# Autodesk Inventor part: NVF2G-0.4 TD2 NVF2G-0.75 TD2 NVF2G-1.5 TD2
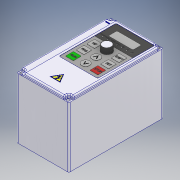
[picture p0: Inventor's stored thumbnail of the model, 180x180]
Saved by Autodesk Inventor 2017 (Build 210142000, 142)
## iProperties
Part Number: NVF2G-0.4 TD2 NVF2G-0.75 TD2 NVF2G-1.5 TD2
Material: Типовые
Document SubType Name: Modeling
Designer: RSagdiev
Density: 1 g/cm^3
Appearance: По умолчанию
Author: RSagdiev
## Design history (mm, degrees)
sketch "Эскиз1"
  geometry: L1 (0, 0)-(44.679, 0) reference; L2 (0, 0)-(0, 56.035) reference; L3 (0, 0)-(154, 0); L4 (154, 0)-(154, 98.6); L5 (154, 98.6)-(0, 98.6); L6 (0, 98.6)-(0, 0)
  constraints: 12 end point, 3 horizontal, 2 parallel, 2 vertical, 1 perpendicular
  dimensions: "d0" = 154 distance of L5.end L4.end; "d1" = 98.6 distance of L4.end L3.end
extrude "Выдавливание1" new body sketch "Эскиз1" stored distance "d2" = 85; taper "d3" = 0 deg
sketch "Эскиз2"
  geometry: L1 (0, 0)-(0, 154) reference; L2 (85, 0)-(85, 154) reference; L3 (0, 154)-(7, 154); L4 (85, 154)-(85, 147); L5 (85, 0)-(78, 0); L6 (0, 0)-(0, 7); L7 (0, 154)-(85, 154) reference; L8 (0, 154)-(7, 154); L9 (7, 154)-(7, 147); L10 (7, 147)-(0, 147); L11 (0, 147)-(0, 154); L12 (85, 154)-(78, 154); L13 (78, 154)-(78, 147); L14 (78, 147)-(85, 147); L15 (85, 147)-(85, 154); L16 (0, 0)-(85, 0) reference; L17 (0, 0)-(7, 0); L18 (7, 0)-(7, 7); L19 (7, 7)-(0, 7); L20 (0, 7)-(0, 0); L21 (85, 0)-(78, 0); L22 (78, 0)-(78, 7); L23 (78, 7)-(85, 7); L24 (85, 7)-(85, 0); L25 (7, 154)-(78, 154); L26 (0, 147)-(0, 154); L27 (78, 154)-(85, 154); L28 (85, 147)-(85, 7); L29 (78, 0)-(7, 0); L30 (85, 7)-(85, 0); L31 (7, 0)-(0, 0); L32 (0, 7)-(0, 147); 1 further point
  constraints: 56 end point, 26 parallel, 13 perpendicular, 7 horizontal
  dimensions: "d4" = 7 distance of L9.end L10.end; "d5" = 7 distance of L3.end L9.end (= d4); "d6" = 7 distance of L4.end L13.end (= d4); "d7" = 7 distance of L13.end L12.end (= d4); "d8" = 7 distance of L6.end L18.end (= d4); "d9" = 7 distance of L18.end L17.end (= d4); "d10" = 7 distance of L22.end L23.end (= d4); "d11" = 7 distance of L5.end L22.end (= d4)
extrude "Выдавливание2" new body sketch "Эскиз2" distance "d12" = 4; taper "d13" = 0 deg
chamfer "Фаска1" distance "d14" = 4; stored, may be unused: second distance "d15" = 2, angle "d16" = 45 deg
sketch "Эскиз3"
  geometry: L1 (7, 150)-(11.5, 150); L2 (7, 150)-(7, 147); L3 (7, 147)-(0, 147); L4 (0, 147)-(0, 7); L5 (0, 7)-(7, 7); L6 (7, 7)-(7, 0); L7 (7, 0)-(11.5, 0); L8 (78, 0)-(78, 7); L9 (78, 7)-(85, 7); L10 (85, 7)-(85, 147); L11 (85, 147)-(78, 147); L12 (78, 147)-(78, 150); L13 (7, 150)-(78, 150) reference; L14 (11.5, 150)-(11.5, 0); L15 (0, 0)-(85, 0) reference; L16 (11.5, 150)-(78, 150); L17 (11.5, 0)-(78, 0); 1 further point
  constraints: 10 end point, 2 perpendicular, 2 point on line
  dimensions: "d19" = 73.5 distance between parallel lines of L14 L10
extrude "Выдавливание3" new body sketch "Эскиз3" distance "d17" = 2; taper "d18" = 0 deg
sketch "Эскиз4"
  geometry: L1 (78, 145)-(19, 145); L2 (17, 143)-(17, 54); L3 (19, 52)-(78, 52); L4 (80, 54)-(80, 143); L5 (85, 7)-(85, 147) reference; L6 (7, 150)-(78, 150) reference; A1 r 2 centre (19, 143) between (19, 145) and (17, 143); A2 r 2 centre (78, 143) between (80, 143) and (78, 145); A3 r 2 centre (78, 54) between (78, 52) and (80, 54); A4 r 2 centre (19, 54) between (17, 54) and (19, 52); 4 further points
  constraints: 8 end point, 8 point on circle, 8 tangent, 6 point on line, 4 centre point, 3 equal radius, 2 parallel, 1 horizontal, 1 perpendicular
  dimensions: "d20" = 63 distance of point (80, 52) point (17, 52); "d21" = 93 distance of point (17, 52) point (17, 145); "d22" = 5 distance between parallel lines of L4 L5; "d23" = 5 distance between parallel lines of L6 L1; "d24" = 2 radius of A1
extrude "Выдавливание4" cut sketch "Эскиз4" distance "d25" = 0.6; taper "d26" = 0 deg
sketch "Эскиз5"
  geometry: L1 (0, 154)-(85, 154) reference; L2 (0, 0)-(0, 154) reference; L3 (85, 154)-(85, 0) reference; L4 (0, 0)-(85, 0) reference; C1 r 2.5 at (4.5, 150.5); C2 r 2.5 at (80.5, 150.5); C3 r 2.5 at (4.5, 3.5); C4 r 2.5 at (80.5, 3.5); 1 further point
  constraints: 4 centre point
  dimensions: "d27" = 5 diameter of C1; "d28" = 3.5 distance from line of C1.centre L1; "d29" = 4.5 distance from line of C1.centre L2; "d30" = 5 diameter of C2; "d31" = 3.5 distance from line of C2.centre L1; "d32" = 4.5 distance from line of C2.centre L3; "d33" = 5 diameter of C3; "d34" = 3.5 distance from line of L4 C3.centre; "d35" = 4.5 distance from line of C3.centre L2; "d36" = 5 diameter of C4; "d37" = 4.5 distance from line of C4.centre L3; "d38" = 3.5 distance from line of C4.centre L4
extrude "Выдавливание5" cut sketch "Эскиз5" stored distance "d39" = 0.6; taper "d40" = 0 deg
fillet "Сопряжение1" dims "d41" = 2
fillet "Сопряжение2" dims "d42" = 2
sketch "Эскиз6"
  geometry: L1 (17, 54)-(17, 110); L2 (78, 52)-(19, 52); L3 (80, 143)-(80, 110); L4 (19, 145)-(78, 145); L5 (17, 54)-(17, 143) reference; L6 (17, 110)-(80, 110); L7 (80, 143)-(80, 54) reference; L8 (17, 110)-(17, 143); L9 (80, 110)-(80, 54); L10 (30.5, 121)-(66.5, 121); L11 (68.5, 123)-(68.5, 133); L12 (66.5, 135)-(30.5, 135); L13 (28.5, 133)-(28.5, 123); L14 (28.5, 121)-(68.5, 135); L15 (68.5, 121)-(28.5, 135); L16 (48.5, 98.5)-(48.5, 63.857); L17 (40.25, 98.5)-(40.25, 63.857); L18 (56.75, 63.857)-(56.75, 98.5); L19 (34, 105)-(23, 105); L20 (22, 104)-(22, 93); L21 (23, 92)-(34, 92); L22 (35, 93)-(35, 104); L23 (35, 105)-(22, 92); L24 (22, 105)-(35, 92); L25 (68.5, 123)-(68.5, 58.5); L26 (28.5, 98.5)-(75.409, 98.5); L27 (26.654, 81.179)-(72.729, 81.179); L28 (26.654, 63.857)-(71.963, 63.857); L29 (75, 93)-(75, 104); L30 (63, 92)-(74, 92); L31 (75, 105)-(62, 92); L32 (62, 105)-(75, 92); L33 (62, 104)-(62, 93); L34 (74, 105)-(63, 105); L35 (75, 75.679)-(75, 86.679); L36 (63, 74.679)-(74, 74.679); L37 (75, 87.679)-(62, 74.679); L38 (62, 87.679)-(75, 74.679); L39 (62, 86.679)-(62, 75.679); L40 (74, 87.679)-(63, 87.679); L41 (75, 58.357)-(75, 69.357); L42 (63, 57.357)-(74, 57.357); L43 (75, 70.357)-(62, 57.357); L44 (62, 70.357)-(75, 57.357); L45 (62, 69.357)-(62, 58.357); L46 (74, 70.357)-(63, 70.357); L47 (35, 58.357)-(35, 69.357); L48 (23, 57.357)-(34, 57.357); L49 (35, 70.357)-(22, 57.357); L50 (22, 70.357)-(35, 57.357); L51 (22, 69.357)-(22, 58.357); L52 (34, 70.357)-(23, 70.357); L53 (35, 75.679)-(35, 86.679); L54 (23, 74.679)-(34, 74.679); L55 (35, 87.679)-(22, 74.679); L56 (22, 87.679)-(35, 74.679); L57 (22, 86.679)-(22, 75.679); L58 (34, 87.679)-(23, 87.679); L59 (78, 52)-(19, 52) reference; L60 (80, 143)-(80, 54) reference; C1 r 6.5 at (48.5, 98.5); C2 r 6.5 at (48.5, 63.857); C3 r 6.5 at (48.5, 81.179); A1 r 2 centre (30.5, 133) between (30.5, 135) and (28.5, 133); A2 r 2 centre (66.5, 133) between (68.5, 133) and (66.5, 135); A3 r 2 centre (66.5, 123) between (66.5, 121) and (68.5, 123); A4 r 2 centre (30.5, 123) between (28.5, 123) and (30.5, 121); A5 r 8.25 centre (48.5, 98.5) between (56.75, 98.5) and (40.25, 98.5); A6 r 8.25 centre (48.5, 63.857) between (40.25, 63.857) and (56.75, 63.857); A7 r 1 centre (34, 104) between (35, 104) and (34, 105); A8 r 1 centre (34, 93) between (34, 92) and (35, 93); A9 r 1 centre (23, 93) between (22, 93) and (23, 92); A10 r 1 centre (23, 104) between (23, 105) and (22, 104); A11 r 1 centre (74, 93) between (74, 92) and (75, 93); A12 r 1 centre (74, 104) between (75, 104) and (74, 105); A13 r 1 centre (63, 104) between (63, 105) and (62, 104); A14 r 1 centre (63, 93) between (62, 93) and (63, 92); A15 r 1 centre (74, 75.679) between (74, 74.679) and (75, 75.679); A16 r 1 centre (74, 86.679) between (75, 86.679) and (74, 87.679); A17 r 1 centre (63, 86.679) between (63, 87.679) and (62, 86.679); A18 r 1 centre (63, 75.679) between (62, 75.679) and (63, 74.679); A19 r 1 centre (74, 58.357) between (74, 57.357) and (75, 58.357); A20 r 1 centre (74, 69.357) between (75, 69.357) and (74, 70.357); A21 r 1 centre (63, 69.357) between (63, 70.357) and (62, 69.357); A22 r 1 centre (63, 58.357) between (62, 58.357) and (63, 57.357); A23 r 1 centre (34, 58.357) between (34, 57.357) and (35, 58.357); A24 r 1 centre (34, 69.357) between (35, 69.357) and (34, 70.357); A25 r 1 centre (23, 69.357) between (23, 70.357) and (22, 69.357); A26 r 1 centre (23, 58.357) between (22, 58.357) and (23, 57.357); A27 r 1 centre (34, 75.679) between (34, 74.679) and (35, 75.679); A28 r 1 centre (34, 86.679) between (35, 86.679) and (34, 87.679); A29 r 1 centre (23, 86.679) between (23, 87.679) and (22, 86.679); A30 r 1 centre (23, 75.679) between (22, 75.679) and (23, 74.679); A31 r 2 centre (19, 143) between (19, 145) and (17, 143) reference; A32 r 2 centre (78, 143) between (80, 143) and (78, 145) reference; A33 r 2 centre (78, 54) between (78, 52) and (80, 54) reference; A34 r 2 centre (19, 54) between (17, 54) and (19, 52) reference; 13 further points
  constraints: 110 end point, 68 point on line, 60 point on circle, 60 tangent, 33 centre point, 21 equal radius, 15 midpoint, 15 parallel, 11 horizontal, 7 perpendicular, 3 coincident, 2 vertical
  dimensions: "d43" = 35 distance between parallel lines of L4 L6; "d44" = 40 distance of L15.end L14.end; "d45" = 14 distance of L14.end L15.start; "d46" = 10 distance between parallel lines of L4 L12; "d47" = 2 radius of A1; "d48" = 11.5 distance between parallel lines of L8 L13; "d49" = 16.5 diameter of A6; "d50" = 31.5 distance between parallel lines of L1 L16; "d51" = 11.5 distance from line of L6 L16.start; "d52" = 11.85714 distance from line of L2 L16.end; "d53" = 13 diameter of C1; "d54" = 13 diameter of C2; "d55" = 13 diameter of C3; "d56" = 13 distance of L24.end L23.end; "d57" = 13 distance of L23.end L24.start; "d58" = 1 radius of A7 (derived); "d59" = 11.5 distance from line of L6 L26.start; "d60" = 11.5 distance from line of L5 L26.start; "d61" = 13 distance of L32.end L31.end; "d62" = 13 distance of L31.end L32.start; "d63" = 1 radius of A12 (derived); "d64" = 13 distance of L38.end L37.end; "d65" = 13 distance of L37.end L38.start; "d66" = 1 radius of A16 (derived); "d67" = 13 distance of L44.end L43.end; "d68" = 13 distance of L43.end L44.start; "d69" = 1 radius of A20 (derived); "d70" = 13 distance of L50.end L49.end; "d71" = 13 distance of L49.end L50.start; "d72" = 1 radius of A24 (derived); "d73" = 13 distance of L56.end L55.end; "d74" = 13 distance of L55.end L56.start; "d75" = 1 radius of A28 (derived)
extrude "Выдавливание6" new body sketch "Эскиз6" distance "d76" = 0.3; taper "d77" = 0 deg
extrude "Выдавливание7" new body sketch "Эскиз6" distance "d78" = 0.6; taper "d79" = 0 deg
sketch "Эскиз7"
  geometry: L1 (17, 110)-(80, 110) reference; L2 (80, 143)-(80, 54) reference; L3 (17, 110)-(80, 110); L4 (80, 110)-(80, 110.1); L5 (80, 110.1)-(17, 110.1); L6 (17, 110.1)-(17, 110); 1 further point
  constraints: 8 end point, 2 parallel, 1 horizontal, 1 perpendicular, 1 point on line
  dimensions: "d80" = 0.1 distance of L4.end L3.end
extrude "Выдавливание8" cut sketch "Эскиз7" distance "d81" = 0.3; taper "d82" = 0 deg
sketch "Эскиз8" dims "d91" = 10
  geometry: L1 (17, 110.1)-(80, 110.1) reference; L2 (17, 54)-(17, 143) reference; C1 r 1 at (25, 115.1); C2 r 1 at (32.75, 115.1); C3 r 1 at (40.5, 115.1); C4 r 1 at (48.25, 115.1); C5 r 1 at (56, 115.1); C6 r 1 at (63.75, 115.1); C7 r 1 at (71.5, 115.1); 1 further point
  constraints: 7 centre point, 1 horizontal, 12 other
  dimensions: "d83" = 2 diameter of C1; "d84" = 5 distance from line of C1.centre L1; "d85" = 8 distance from line of C1.centre L2; "d88" = 7.75 distance of C1.centre C2.centre
extrude "Выдавливание9" join sketch "Эскиз8" distance "d93" = 0.3; taper "d94" = 0 deg
sketch "Эскиз9"
  geometry: C1 r 6.5 at (0, 0) reference; C2 r 7.5 at (0, 0); 1 further point
  constraints: 1 centre point, 1 coincident
  dimensions: "d95" = 15 diameter of C2
extrude "Выдавливание10" join sketch "Эскиз9" distance "d96" = 9.4; taper "d97" = -3 deg
sketch "Эскиз10"
  geometry: L1 (0, 7.331)-(0.619, 6.259); L2 (0.619, 6.259)-(-0.619, 6.259); L3 (-0.619, 6.259)-(0, 7.331); 2 further points
  constraints: 6 end point, 7 other
sketch "Эскиз11"
  geometry: L1 (0, 7.917)-(0.884, 6.386); L2 (0.884, 6.386)-(-0.884, 6.386); L3 (-0.884, 6.386)-(0, 7.917); 2 further points
  constraints: 6 end point, 7 other
feature "Лофт1" sketch "Эскиз10", "Эскиз11" dims "d98" = 0, "d99" = 90 deg, "d100" = 0, "d101" = 90 deg
sketch "Эскиз12"
  geometry: L1 (25.404, 100.254)-(31.624, 100.254); L2 (31.624, 100.254)-(31.624, 96.754); L3 (31.624, 96.754)-(25.404, 96.754); L4 (25.404, 96.754)-(25.404, 100.254); L5 (24.455, 83.155)-(33.309, 83.155); L6 (33.309, 83.155)-(33.309, 79.524); L7 (33.309, 79.524)-(24.455, 79.524); L8 (24.455, 79.524)-(24.455, 83.155); L9 (24.098, 65.818)-(33.455, 65.818); L10 (33.455, 65.818)-(33.455, 62.245); L11 (33.455, 62.245)-(24.098, 62.245); L12 (24.098, 62.245)-(24.098, 65.818); L13 (62.927, 65.818)-(74.479, 65.818); L14 (74.479, 65.818)-(74.479, 62.171); L15 (74.479, 62.171)-(62.927, 62.171); L16 (62.927, 62.171)-(62.927, 65.818); L17 (64.708, 83.036)-(72.902, 83.036); L18 (72.902, 83.036)-(72.902, 79.411); L19 (72.902, 79.411)-(64.708, 79.411); L20 (64.708, 79.411)-(64.708, 83.036); L21 (62.808, 100.372)-(75.858, 100.372); L22 (75.858, 100.372)-(75.858, 96.748); L23 (75.858, 96.748)-(62.808, 96.748); L24 (62.808, 96.748)-(62.808, 100.372); 1 further point
  constraints: 12 other
feature "Рельеф1" dims "d105" = 0.1, "d106" = 0
feature "Рельеф2" dims "d107" = 0.1, "d108" = 0
feature "Рельеф3" dims "d109" = 0.1, "d110" = 0
feature "Рельеф4" dims "d111" = 0.1, "d112" = 0
feature "Рельеф5" dims "d113" = 0.1, "d114" = 0
feature "Рельеф6" dims "d115" = 0.1, "d116" = 0
sketch "Эскиз13"
  geometry: L1 (-3.144, -2.347)-(-0.04, 3.728); L2 (-0.04, 3.728)-(3.298, -2.347); L3 (3.298, -2.347)-(2.096, -2.347); L4 (2.096, -2.347)-(-0.04, 1.541); L5 (-0.04, 1.541)-(-2.027, -2.347); L6 (-2.027, -2.347)-(-3.144, -2.347); L7 (-9.387, -8.657)-(8.031, -8.657); L8 (-3.144, -14.967)-(-0.04, -21.041); L9 (-0.04, -21.041)-(3.298, -14.967); L10 (3.298, -14.967)-(2.096, -14.967); L11 (2.096, -14.967)-(-0.04, -18.855); L12 (-0.04, -18.855)-(-2.027, -14.967); L13 (-2.027, -14.967)-(-3.144, -14.967); 1 further point
  constraints: 26 end point, 6 symmetric about line, 2 horizontal, 2 parallel, 2 point on line, 1 collinear
feature "Рельеф7" dims "d117" = 0.1, "d118" = 0
feature "Рельеф8" dims "d119" = 0.1, "d120" = 0
sketch "Эскиз14"
  geometry: L1 (46.558, 30.23)-(54.854, 15.86); L2 (54.854, 15.86)-(38.261, 15.86); L3 (38.261, 15.86)-(46.558, 30.23); L4 (53.427, 16.684)-(46.558, 28.582); L5 (46.558, 28.582)-(39.688, 16.684); L6 (39.688, 16.684)-(53.427, 16.684); L7 (45.731, 24.915)-(44.79, 21.105); L8 (44.79, 21.105)-(47.211, 21.275); L9 (47.211, 21.275)-(46.17, 18.958); L10 (46.17, 18.958)-(45.221, 19.385); L11 (45.221, 19.385)-(45.377, 17.155); L12 (45.377, 17.155)-(47.847, 18.204); L13 (47.847, 18.204)-(47.167, 18.51); L14 (47.167, 18.51)-(49.096, 22.146); L15 (49.096, 22.146)-(45.941, 21.963); L16 (45.941, 21.963)-(47.507, 24.915); L17 (47.507, 24.915)-(45.731, 24.915); 2 further points
  constraints: 34 end point, 2 perpendicular, 2 point on line, 1 parallel, 9 other
extrude "Выдавливание11" cut sketch "Эскиз14" distance "d121" = 0.1; taper "d122" = 0 deg
extrude "Выдавливание12" join sketch "Эскиз14" distance "d123" = 0.05; taper "d124" = 0 deg
sketch "Эскиз15"
  geometry: L1 (18.688, 119.105)-(43.381, 119.105); L2 (43.381, 119.105)-(43.381, 116.218); L3 (43.381, 116.218)-(18.688, 116.218); L4 (18.688, 116.218)-(18.688, 119.105); L5 (44.422, 118.659)-(75.363, 118.659); L6 (75.363, 118.659)-(75.363, 114.568); L7 (75.363, 114.568)-(44.422, 114.568); L8 (44.422, 114.568)-(44.422, 118.659); 1 further point
  constraints: 4 other
feature "Рельеф9" sketch "Эскиз15" dims "d125" = 0.1, "d126" = 0
sketch "Эскиз16" dims "d133" = 10, "d140" = 10
  geometry: L1 (-46.348, 125.18)-(-46.348, 103.213); L2 (-47.848, 125.18)-(-47.848, 103.213); L3 (-44.848, 103.213)-(-44.848, 125.18); L4 (0, 136)-(4, 136) reference; L5 (-40.348, 125.18)-(-40.348, 103.213); L6 (-41.848, 125.18)-(-41.848, 103.213); L7 (-38.848, 103.213)-(-38.848, 125.18); L8 (-34.348, 125.18)-(-34.348, 103.213); L9 (-35.848, 125.18)-(-35.848, 103.213); L10 (-32.848, 103.213)-(-32.848, 125.18); L11 (-28.348, 125.18)-(-28.348, 103.213); L12 (-29.848, 125.18)-(-29.848, 103.213); L13 (-26.848, 103.213)-(-26.848, 125.18); L14 (-22.348, 125.18)-(-22.348, 103.213); L15 (-23.848, 125.18)-(-23.848, 103.213); L16 (-20.848, 103.213)-(-20.848, 125.18); L17 (-47.848, 95.18)-(-47.848, 73.213); L18 (-46.348, 95.18)-(-46.348, 73.213); L19 (-44.848, 73.213)-(-44.848, 95.18); L20 (-41.848, 95.18)-(-41.848, 73.213); L21 (-38.848, 73.213)-(-38.848, 95.18); L22 (-35.848, 95.18)-(-35.848, 73.213); L23 (-34.348, 95.18)-(-34.348, 73.213); L24 (-32.848, 73.213)-(-32.848, 95.18); L25 (-29.848, 95.18)-(-29.848, 73.213); L26 (-28.348, 95.18)-(-28.348, 73.213); L27 (-26.848, 73.213)-(-26.848, 95.18); L28 (-23.848, 95.18)-(-23.848, 73.213); L29 (-22.348, 95.18)-(-22.348, 73.213); L30 (-20.848, 73.213)-(-20.848, 95.18); L31 (-40.348, 95.18)-(-40.348, 73.213); L32 (-47.848, 65.18)-(-47.848, 43.213); L33 (-46.348, 65.18)-(-46.348, 43.213); L34 (-44.848, 43.213)-(-44.848, 65.18); L35 (-41.848, 65.18)-(-41.848, 43.213); L36 (-38.848, 43.213)-(-38.848, 65.18); L37 (-35.848, 65.18)-(-35.848, 43.213); L38 (-34.348, 65.18)-(-34.348, 43.213); L39 (-32.848, 43.213)-(-32.848, 65.18); L40 (-29.848, 65.18)-(-29.848, 43.213); L41 (-28.348, 65.18)-(-28.348, 43.213); L42 (-26.848, 43.213)-(-26.848, 65.18); L43 (-23.848, 65.18)-(-23.848, 43.213); L44 (-22.348, 65.18)-(-22.348, 43.213); L45 (-20.848, 43.213)-(-20.848, 65.18); L46 (-40.348, 65.18)-(-40.348, 43.213); L47 (-47.848, 35.18)-(-47.848, 13.213); L48 (-46.348, 35.18)-(-46.348, 13.213); L49 (-44.848, 13.213)-(-44.848, 35.18); L50 (-41.848, 35.18)-(-41.848, 13.213); L51 (-38.848, 13.213)-(-38.848, 35.18); L52 (-35.848, 35.18)-(-35.848, 13.213); L53 (-34.348, 35.18)-(-34.348, 13.213); L54 (-32.848, 13.213)-(-32.848, 35.18); L55 (-29.848, 35.18)-(-29.848, 13.213); L56 (-28.348, 35.18)-(-28.348, 13.213); L57 (-26.848, 13.213)-(-26.848, 35.18); L58 (-23.848, 35.18)-(-23.848, 13.213); L59 (-22.348, 35.18)-(-22.348, 13.213); L60 (-20.848, 13.213)-(-20.848, 35.18); L61 (-40.348, 35.18)-(-40.348, 13.213); A1 r 1.5 centre (-46.348, 125.18) between (-44.848, 125.18) and (-47.848, 125.18); A2 r 1.5 centre (-46.348, 103.213) between (-47.848, 103.213) and (-44.848, 103.213); A3 r 1.5 centre (-40.348, 125.18) between (-38.848, 125.18) and (-41.848, 125.18); A4 r 1.5 centre (-40.348, 103.213) between (-41.848, 103.213) and (-38.848, 103.213); A5 r 1.5 centre (-34.348, 125.18) between (-32.848, 125.18) and (-35.848, 125.18); A6 r 1.5 centre (-34.348, 103.213) between (-35.848, 103.213) and (-32.848, 103.213); A7 r 1.5 centre (-28.348, 125.18) between (-26.848, 125.18) and (-29.848, 125.18); A8 r 1.5 centre (-28.348, 103.213) between (-29.848, 103.213) and (-26.848, 103.213); A9 r 1.5 centre (-22.348, 125.18) between (-20.848, 125.18) and (-23.848, 125.18); A10 r 1.5 centre (-22.348, 103.213) between (-23.848, 103.213) and (-20.848, 103.213); A11 r 1.5 centre (-46.348, 73.213) between (-47.848, 73.213) and (-44.848, 73.213); A12 r 1.5 centre (-40.348, 95.18) between (-38.848, 95.18) and (-41.848, 95.18); A13 r 1.5 centre (-46.348, 95.18) between (-44.848, 95.18) and (-47.848, 95.18); A14 r 1.5 centre (-34.348, 95.18) between (-32.848, 95.18) and (-35.848, 95.18); A15 r 1.5 centre (-22.348, 95.18) between (-20.848, 95.18) and (-23.848, 95.18); A16 r 1.5 centre (-28.348, 95.18) between (-26.848, 95.18) and (-29.848, 95.18); A17 r 1.5 centre (-40.348, 73.213) between (-41.848, 73.213) and (-38.848, 73.213); A18 r 1.5 centre (-34.348, 73.213) between (-35.848, 73.213) and (-32.848, 73.213); A19 r 1.5 centre (-28.348, 73.213) between (-29.848, 73.213) and (-26.848, 73.213); A20 r 1.5 centre (-22.348, 73.213) between (-23.848, 73.213) and (-20.848, 73.213); A21 r 1.5 centre (-46.348, 43.213) between (-47.848, 43.213) and (-44.848, 43.213); A22 r 1.5 centre (-40.348, 65.18) between (-38.848, 65.18) and (-41.848, 65.18); A23 r 1.5 centre (-46.348, 65.18) between (-44.848, 65.18) and (-47.848, 65.18); A24 r 1.5 centre (-34.348, 65.18) between (-32.848, 65.18) and (-35.848, 65.18); A25 r 1.5 centre (-22.348, 65.18) between (-20.848, 65.18) and (-23.848, 65.18); A26 r 1.5 centre (-28.348, 65.18) between (-26.848, 65.18) and (-29.848, 65.18); A27 r 1.5 centre (-40.348, 43.213) between (-41.848, 43.213) and (-38.848, 43.213); A28 r 1.5 centre (-34.348, 43.213) between (-35.848, 43.213) and (-32.848, 43.213); A29 r 1.5 centre (-28.348, 43.213) between (-29.848, 43.213) and (-26.848, 43.213); A30 r 1.5 centre (-22.348, 43.213) between (-23.848, 43.213) and (-20.848, 43.213); A31 r 1.5 centre (-46.348, 13.213) between (-47.848, 13.213) and (-44.848, 13.213); A32 r 1.5 centre (-40.348, 35.18) between (-38.848, 35.18) and (-41.848, 35.18); A33 r 1.5 centre (-46.348, 35.18) between (-44.848, 35.18) and (-47.848, 35.18); A34 r 1.5 centre (-34.348, 35.18) between (-32.848, 35.18) and (-35.848, 35.18); A35 r 1.5 centre (-22.348, 35.18) between (-20.848, 35.18) and (-23.848, 35.18); A36 r 1.5 centre (-28.348, 35.18) between (-26.848, 35.18) and (-29.848, 35.18); A37 r 1.5 centre (-40.348, 13.213) between (-41.848, 13.213) and (-38.848, 13.213); A38 r 1.5 centre (-34.348, 13.213) between (-35.848, 13.213) and (-32.848, 13.213); A39 r 1.5 centre (-28.348, 13.213) between (-29.848, 13.213) and (-26.848, 13.213); A40 r 1.5 centre (-22.348, 13.213) between (-23.848, 13.213) and (-20.848, 13.213); 22 further points
  constraints: 160 end point, 80 point on circle, 40 centre point, 4 tangent, 2 vertical, 1 collinear, 1 horizontal, 1 midpoint, 1 parallel, 227 other
  dimensions: "d127" = 3 diameter of A2; "d130" = 6 distance of L2.start L6.start; "d137" = 30 distance of L6.end L20.end
extrude "Выдавливание13" cut sketch "Эскиз16" distance "d142" = 18.55; taper "d143" = 0 deg
sketch "Эскиз17"
  geometry: L1 (3.833, 141.986)-(10.833, 141.986); L2 (10.833, 141.986)-(10.833, 139.917); L3 (10.833, 139.917)-(3.833, 139.917); L4 (3.833, 139.917)-(3.833, 141.986); 1 further point
  constraints: 2 other
feature "Рельеф10" sketch "Эскиз17" dims "d144" = 0.1, "d145" = 0
node "Твердое тело1"
pattern_circular "Круговой массив1" dims angle "d103" = 360 deg
node "Твердое тело2"
node "Твердое тело3"
node "Твердое тело4"
node "Твердое тело5"
